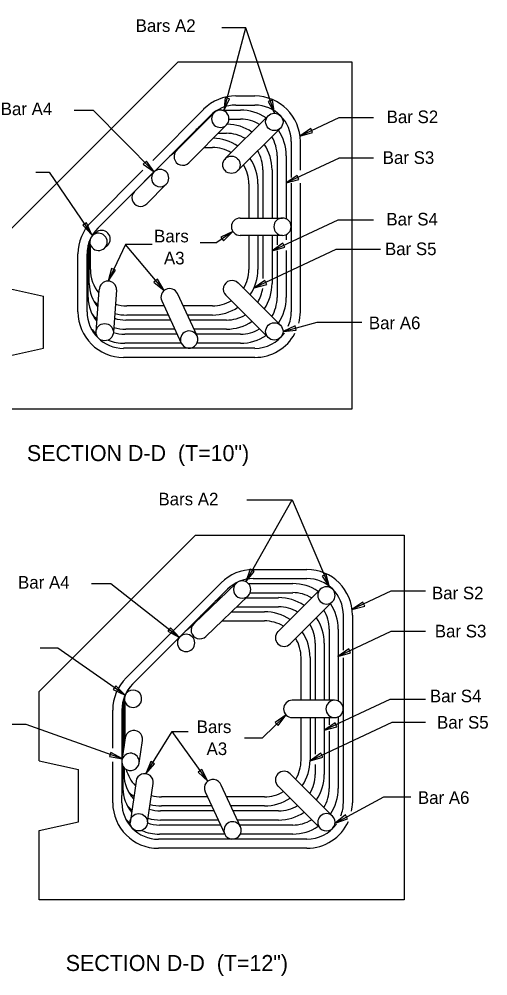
# Model space of a CAD drawing. Extents: x 0.4 to 30.8, y 0.2 to 19.4.
# Drawn here: x 9.71 to 15.33, y 0.99 to 12.47 of the extents above; entities that cross this region are included whole.
import ezdxf

# ---------------------------------------------------------------- set-up
doc = ezdxf.new("R2010")
doc.units = 0
for name, color, linetype in [('Dimension', 7, 'Continuous'), ('Rebar', 7, 'Continuous'), ('SheetPileConc', 7, 'Continuous'), ('TextStructures', 7, 'Continuous')]:
    doc.layers.add(name, color=color, linetype=linetype)

msp = doc.modelspace()

# ---------------------------------------------------------------- linework, layer by layer
at = {"layer": 'Dimension'}
for p, q in [((12.427, 12.366), (12.138, 12.366)), ((12.163, 11.368), (12.427, 12.366)), ((12.767, 11.341), (12.427, 12.366)), ((10.597, 11.375), (10.367, 11.375)), ((11.324, 10.637), (10.597, 11.375)), ((13.54, 11.285), (13.073, 11.066)), ((13.956, 11.285), (13.54, 11.285)), ((13.545, 10.803), (12.909, 10.505)), ((13.956, 10.803), (13.54, 10.803)), ((9.905, 10.633), (10.066, 10.633)), ((10.066, 10.633), (10.579, 9.884)), ((13.528, 10.06), (12.74, 9.69)), ((13.956, 10.06), (13.528, 10.06)), ((12.271, 9.922), (12.076, 9.789)), ((10.98, 9.767), (10.772, 9.327)), ((11.301, 9.767), (10.98, 9.767)), ((11.444, 9.214), (10.98, 9.767)), ((11.877, 9.789), (12.076, 9.789)), ((13.506, 9.707), (12.524, 9.246)), ((14.041, 9.707), (13.506, 9.707)), ((12.871, 8.724), (13.28, 8.834)), ((13.28, 8.834), (13.815, 8.834)), ((12.425, 5.722), (12.979, 6.704)), ((12.437, 6.704), (12.979, 6.704)), ((12.979, 6.704), (13.427, 5.656)), ((10.805, 5.696), (10.575, 5.696)), ((11.627, 5.052), (10.805, 5.696)), ((14.165, 5.607), (13.698, 5.388)), ((14.581, 5.607), (14.165, 5.607)), ((14.165, 5.124), (13.529, 4.826)), ((14.581, 5.124), (14.165, 5.124)), ((10.172, 4.926), (9.958, 4.926)), ((10.978, 4.362), (10.172, 4.926)), ((14.153, 4.311), (13.365, 3.941)), ((14.581, 4.311), (14.153, 4.311)), ((12.908, 4.125), (12.625, 3.849)), ((14.175, 4.033), (13.196, 3.573)), ((14.581, 4.033), (14.175, 4.033)), ((9.791, 4.01), (9.609, 4.01)), ((10.944, 3.596), (9.791, 4.01)), ((11.226, 3.419), (11.542, 3.925)), ((11.542, 3.925), (11.734, 3.925)), ((11.969, 3.33), (11.542, 3.925)), ((12.408, 3.849), (12.625, 3.849)), ((13.496, 2.828), (14.08, 3.141)), ((14.08, 3.141), (14.403, 3.141))]:
    msp.add_line(p, q, dxfattribs=at)
for points in [[(12.163, 11.368), (12.228, 11.512), (12.177, 11.526)], [(12.767, 11.341), (12.743, 11.497), (12.693, 11.481)], [(13.073, 11.066), (13.226, 11.109), (13.203, 11.157)], [(11.324, 10.637), (11.233, 10.767), (11.195, 10.73)], [(12.909, 10.505), (13.062, 10.547), (13.039, 10.595)], [(10.579, 9.884), (10.513, 10.028), (10.469, 9.998)], [(12.271, 9.922), (12.127, 9.856), (12.157, 9.812)], [(12.74, 9.69), (12.892, 9.733), (12.87, 9.781)], [(10.772, 9.327), (10.863, 9.457), (10.815, 9.48)], [(11.444, 9.214), (11.364, 9.35), (11.323, 9.316)], [(12.524, 9.246), (12.676, 9.288), (12.654, 9.336)], [(12.871, 8.724), (13.029, 8.739), (13.015, 8.79)], [(12.425, 5.722), (12.524, 5.845), (12.478, 5.871)], [(13.427, 5.656), (13.387, 5.809), (13.339, 5.788)], [(13.698, 5.388), (13.851, 5.43), (13.828, 5.478)], [(11.628, 5.052), (11.521, 5.17), (11.488, 5.128)], [(13.529, 4.826), (13.682, 4.868), (13.659, 4.916)], [(10.978, 4.363), (10.865, 4.474), (10.835, 4.43)], [(12.908, 4.125), (12.777, 4.035), (12.814, 3.997)], [(13.365, 3.941), (13.518, 3.983), (13.495, 4.031)], [(10.944, 3.596), (10.806, 3.673), (10.788, 3.624)], [(11.226, 3.419), (11.331, 3.538), (11.287, 3.566)], [(13.196, 3.573), (13.348, 3.616), (13.326, 3.664)], [(11.969, 3.33), (11.896, 3.47), (11.853, 3.438)], [(13.496, 2.828), (13.646, 2.879), (13.621, 2.925)]]:
    msp.add_lwpolyline(points, close=True, dxfattribs=at)
at = {"layer": 'Rebar'}
for p, q in [((12.306, 11.548), (12.532, 11.548)), ((11.92, 11.388), (11.308, 10.775)), ((12.137, 11.378), (12.362, 11.378)), ((12.306, 11.438), (12.532, 11.438)), ((12.045, 11.347), (11.601, 10.9)), ((11.997, 11.31), (11.722, 11.035)), ((12.179, 10.796), (12.694, 11.31)), ((12.223, 11.269), (12.362, 11.269)), ((11.828, 11.141), (10.65, 9.963)), ((12.192, 11.2), (11.742, 10.747)), ((12.327, 10.649), (12.841, 11.163)), ((12.092, 11.1), (12.193, 11.1)), ((11.607, 10.907), (11.594, 10.893)), ((11.924, 10.931), (12.024, 10.931)), ((12.969, 11.001), (12.969, 10.57)), ((13.078, 11.001), (13.078, 10.656)), ((12.8, 10.831), (12.8, 10.084)), ((12.909, 10.831), (12.909, 10.074)), ((11.188, 10.656), (10.572, 10.04)), ((11.089, 10.402), (11.323, 10.636)), ((12.63, 10.662), (12.63, 10.084)), ((12.74, 10.662), (12.74, 10.084)), ((11.236, 10.255), (11.471, 10.489)), ((12.461, 10.493), (12.461, 10.084)), ((12.571, 10.493), (12.571, 10.084)), ((12.969, 10.501), (12.969, 8.959)), ((13.078, 10.503), (13.078, 8.959)), ((12.357, 10.084), (12.865, 10.084)), ((10.624, 9.908), (10.587, 9.874)), ((12.865, 9.876), (12.357, 9.876)), ((12.461, 9.876), (12.461, 9.467)), ((12.571, 9.876), (12.571, 9.467)), ((12.63, 9.876), (12.63, 9.358)), ((12.74, 9.876), (12.74, 9.298)), ((12.8, 9.876), (12.8, 9.762)), ((12.909, 9.886), (12.909, 9.821)), ((10.534, 9.129), (10.534, 9.759)), ((10.547, 9.428), (10.547, 9.802)), ((10.56, 9.467), (10.56, 9.762)), ((10.729, 9.722), (10.768, 9.758)), ((10.412, 8.959), (10.412, 9.653)), ((10.521, 9.047), (10.521, 9.653)), ((12.8, 9.689), (12.8, 9.129)), ((12.909, 9.694), (12.909, 9.129)), ((10.547, 9.298), (10.547, 9.428)), ((12.333, 9.305), (12.841, 8.797)), ((10.628, 8.715), (10.667, 9.223)), ((10.875, 9.223), (10.836, 8.715)), ((11.416, 9.09), (11.651, 8.582)), ((11.84, 8.67), (11.605, 9.178)), ((12.694, 8.65), (12.186, 9.158)), ((10.521, 8.959), (10.521, 9.047)), ((11.444, 9.03), (10.998, 9.03)), ((12.024, 9.03), (11.674, 9.03)), ((11.522, 8.86), (10.985, 8.86)), ((11.495, 8.92), (10.998, 8.92)), ((12.024, 8.92), (11.724, 8.92)), ((12.193, 8.86), (11.752, 8.86)), ((11.573, 8.751), (10.985, 8.751)), ((12.193, 8.751), (11.802, 8.751)), ((11.6, 8.691), (10.972, 8.691)), ((12.362, 8.691), (11.83, 8.691)), ((12.532, 8.522), (10.959, 8.522)), ((11.651, 8.582), (10.972, 8.582)), ((12.362, 8.582), (11.839, 8.582)), ((12.532, 8.413), (10.959, 8.413)), ((12.515, 5.869), (13.157, 5.869)), ((12.515, 5.76), (13.157, 5.76)), ((12.128, 5.709), (10.989, 4.57)), ((11.401, 4.828), (12.205, 5.631)), ((12.309, 5.703), (11.806, 5.22)), ((12.456, 5.7), (12.987, 5.7)), ((12.811, 5.124), (13.319, 5.631)), ((11.947, 5.066), (12.453, 5.552)), ((12.43, 5.53), (12.818, 5.53)), ((12.478, 5.59), (12.987, 5.59)), ((12.316, 5.421), (12.818, 5.421)), ((13.466, 5.484), (12.958, 4.976)), ((11.93, 5.356), (11.765, 5.191)), ((12.254, 5.361), (12.649, 5.361)), ((13.594, 5.322), (13.594, 4.903)), ((13.703, 5.322), (13.703, 3.072)), ((11.765, 5.191), (11.066, 4.492)), ((12.14, 5.252), (12.649, 5.252)), ((13.425, 5.153), (13.425, 4.301)), ((13.534, 5.153), (13.534, 4.291)), ((13.256, 4.984), (13.256, 4.301)), ((13.365, 4.984), (13.365, 4.301)), ((13.086, 4.814), (13.086, 4.301)), ((13.196, 4.814), (13.196, 4.301)), ((13.594, 4.811), (13.594, 3.072)), ((10.964, 4.302), (10.964, 3.75)), ((10.977, 3.835), (10.977, 4.276)), ((13.49, 4.301), (12.982, 4.301)), ((10.829, 3.727), (10.829, 4.183)), ((10.938, 4.183), (10.938, 3.16)), ((10.951, 4.196), (10.951, 3.659)), ((12.982, 4.093), (13.49, 4.093)), ((13.086, 4.093), (13.086, 3.58)), ((13.196, 4.093), (13.196, 3.58)), ((13.256, 4.093), (13.256, 3.655)), ((13.365, 4.093), (13.365, 3.411)), ((13.425, 4.093), (13.425, 4.004)), ((13.534, 4.103), (13.534, 3.242)), ((13.425, 3.928), (13.425, 3.242)), ((10.978, 3.849), (10.939, 3.575)), ((11.145, 3.546), (11.184, 3.819)), ((10.829, 3.072), (10.829, 3.561)), ((10.951, 3.51), (10.951, 3.242)), ((10.964, 3.492), (10.964, 3.411)), ((13.256, 3.53), (13.256, 3.411)), ((11.108, 3.331), (11.036, 2.83)), ((13.466, 2.91), (12.958, 3.418)), ((11.244, 2.844), (11.314, 3.301)), ((12.361, 2.783), (12.13, 3.283)), ((12.811, 3.271), (13.319, 2.763)), ((10.938, 3.072), (10.938, 3.16)), ((11.965, 3.143), (11.415, 3.143)), ((11.937, 3.203), (12.172, 2.696)), ((12.649, 3.143), (12.195, 3.143)), ((12.016, 3.033), (11.415, 3.033)), ((12.649, 3.033), (12.245, 3.033)), ((12.043, 2.973), (11.402, 2.973)), ((12.818, 2.973), (12.273, 2.973)), ((12.121, 2.804), (11.389, 2.804)), ((12.094, 2.864), (11.402, 2.864)), ((12.818, 2.864), (12.323, 2.864)), ((12.987, 2.804), (12.351, 2.804)), ((12.172, 2.695), (11.389, 2.695)), ((12.987, 2.695), (12.36, 2.695)), ((13.157, 2.635), (11.376, 2.635)), ((13.157, 2.526), (11.376, 2.526))]:
    msp.add_line(p, q, dxfattribs=at)
for centre in [(12.767, 11.237), (12.253, 10.722), (10.732, 8.715), (12.767, 8.724), (11.14, 2.837)]:
    msp.add_circle(centre, 0.104, dxfattribs=at)
for centre, radius, start, end in [((12.306, 11.001), 0.547, 90, 134.9913), ((12.532, 11.001), 0.547, 0, 90), ((12.306, 11.001), 0.438, 90, 134.9913), ((12.119, 11.274), 0.104, 315.2149, 135.1708), ((12.137, 10.831), 0.547, 90, 95.9567), ((12.362, 10.831), 0.547, 55.9788, 90), ((12.532, 11.001), 0.438, 0, 90), ((12.119, 11.274), 0.104, 136.4105, 315.2348), ((12.362, 10.831), 0.438, 58.772, 90), ((12.137, 10.831), 0.438, 124.0426, 135), ((11.968, 10.662), 0.547, 96.7693, 98.1366), ((12.193, 10.662), 0.547, 55.9755, 89.1847), ((12.362, 10.831), 0.547, 0, 34.0266), ((11.968, 10.662), 0.438, 123.4477, 135), ((11.799, 10.493), 0.547, 96.6173, 98.1301), ((12.024, 10.493), 0.547, 55.9731, 89.0554), ((12.193, 10.662), 0.438, 58.7678, 90), ((12.362, 10.831), 0.438, 0, 31.2349), ((12.024, 10.493), 0.438, 58.7648, 90), ((12.193, 10.662), 0.547, 0, 34.0233), ((11.799, 10.493), 0.438, 120.5215, 135), ((11.668, 10.82), 0.104, 129.9409, 315.2357), ((12.024, 10.493), 0.547, 0, 34.0209), ((12.193, 10.662), 0.438, 0, 31.2307), ((12.024, 10.493), 0.438, 0, 31.2277), ((11.397, 10.563), 0.104, 135.0001, 315.0045), ((11.397, 10.563), 0.104, 315, 134.9998), ((11.163, 10.328), 0.104, 134.9779, 315.0221), ((10.959, 9.653), 0.547, 135, 180), ((12.357, 9.98), 0.104, 90.0071, 269.9929), ((12.865, 9.98), 0.104, 90.0227, 269.9756), ((12.865, 9.98), 0.104, 270, 90), ((10.959, 9.653), 0.438, 135, 180), ((10.658, 9.798), 0.104, 316.5108, 221.7293), ((10.695, 9.832), 0.104, 315, 132.8745), ((10.658, 9.798), 0.104, 221.7293, 314.4372), ((10.998, 9.467), 0.438, 180, 220.1905), ((12.024, 9.467), 0.438, 328.7684, 360), ((12.024, 9.467), 0.547, 325.9767, 360), ((10.985, 9.298), 0.438, 180, 220.2039), ((10.771, 9.223), 0.104, 0, 180), ((12.259, 9.231), 0.104, 45.0029, 225.0029), ((12.193, 9.298), 0.547, 325.978, 360), ((11.511, 9.134), 0.104, 24.7984, 204.7419), ((12.193, 9.298), 0.438, 328.7701, 352.2986), ((10.972, 9.129), 0.438, 180, 220.1919), ((10.998, 9.467), 0.547, 222.8908, 230.87), ((12.024, 9.467), 0.438, 270, 301.2314), ((12.362, 9.129), 0.438, 328.7717, 360), ((12.362, 9.129), 0.547, 325.9793, 360), ((10.959, 8.959), 0.547, 180, 270), ((10.959, 8.959), 0.438, 180, 270), ((10.998, 9.467), 0.438, 251.8586, 270), ((12.024, 9.467), 0.547, 270, 304.0244), ((12.532, 8.959), 0.438, 336.652, 360), ((12.532, 8.959), 0.547, 345.6268, 360), ((10.985, 9.298), 0.547, 222.9391, 230.8792), ((10.985, 9.298), 0.438, 251.8683, 270), ((10.998, 9.467), 0.547, 254.6455, 270), ((12.193, 9.298), 0.438, 270, 301.233), ((12.193, 9.298), 0.547, 270, 304.0257), ((10.972, 9.129), 0.547, 222.9167, 231.0732), ((10.985, 9.298), 0.547, 254.6532, 270), ((11.745, 8.626), 0.104, 24.7751, 203.3393), ((12.362, 9.129), 0.438, 270, 301.2347), ((10.972, 9.129), 0.547, 248.6363, 270), ((10.972, 9.129), 0.438, 251.8595, 270), ((11.745, 8.626), 0.104, 203.3393, 24.7751), ((12.362, 9.129), 0.547, 270, 304.027), ((12.532, 8.959), 0.438, 270, 324.3324), ((12.532, 8.959), 0.547, 270, 331.8725), ((12.515, 5.322), 0.547, 90, 135), ((13.157, 5.322), 0.547, 0, 90), ((12.515, 5.322), 0.438, 90, 135), ((13.157, 5.322), 0.438, 0, 90), ((12.381, 5.628), 0.104, 135, 315.0245), ((12.381, 5.628), 0.104, 315, 134.9767), ((12.987, 5.153), 0.547, 55.9787, 90), ((13.392, 5.558), 0.104, 135.0039, 315.0039), ((13.392, 5.558), 0.104, 315, 135), ((12.345, 5.153), 0.438, 118.5503, 135), ((12.176, 4.984), 0.547, 95.9443, 98.1301), ((12.818, 4.984), 0.547, 55.9765, 90), ((12.987, 5.153), 0.438, 58.7718, 90), ((12.818, 4.984), 0.438, 58.769, 90), ((12.987, 5.153), 0.547, 0, 34.0248), ((12.176, 4.984), 0.438, 121.166, 135), ((12.007, 4.814), 0.547, 95.9667, 98.1301), ((12.649, 4.814), 0.547, 55.9766, 90), ((12.818, 4.984), 0.547, 0, 34.0221), ((12.987, 5.153), 0.438, 0, 31.2323), ((12.007, 4.814), 0.438, 121.08, 135), ((11.912, 5.043), 0.208, 118.7822, 135), ((11.873, 5.14), 0.104, 130.2199, 315.0091), ((12.649, 4.814), 0.438, 58.7692, 90), ((12.818, 4.984), 0.438, 0, 31.2289), ((11.709, 4.988), 0.104, 135.0001, 315), ((11.709, 4.988), 0.104, 315.0002, 134.9995), ((12.884, 5.05), 0.104, 134.9993, 314.9804), ((12.649, 4.814), 0.547, 0, 34.0217), ((12.649, 4.814), 0.438, 0, 31.2301), ((11.376, 4.183), 0.547, 135, 180), ((11.376, 4.183), 0.438, 135, 180), ((11.389, 4.196), 0.438, 135, 153.6351), ((11.072, 4.319), 0.104, 315, 225.1883), ((11.389, 4.196), 0.438, 163.9734, 180), ((12.982, 4.197), 0.104, 90.0337, 269.9664), ((13.49, 4.197), 0.104, 90.0227, 269.9754), ((13.49, 4.197), 0.104, 270, 90), ((11.072, 4.319), 0.104, 225.1883, 314.9716), ((11.081, 3.834), 0.104, 351.8606, 171.8873), ((11.042, 3.561), 0.104, 351.8732, 231.3288), ((12.649, 3.58), 0.438, 328.7552, 0), ((12.649, 3.58), 0.547, 325.9681, 0), ((11.042, 3.561), 0.104, 231.3288, 351.8732), ((11.415, 3.58), 0.438, 194.6287, 223.9951), ((12.884, 3.345), 0.104, 45.014, 225.0062), ((11.402, 3.411), 0.438, 180, 222.1318), ((11.211, 3.316), 0.104, 351.2929, 171.8392), ((12.032, 3.247), 0.104, 20.0236, 204.7419), ((12.818, 3.411), 0.438, 328.7619, 360), ((12.818, 3.411), 0.547, 325.9733, 360), ((11.389, 3.242), 0.438, 180, 220.1986), ((12.987, 3.242), 0.438, 328.7685, 360), ((12.987, 3.242), 0.547, 325.9785, 360), ((11.415, 3.58), 0.547, 222.8885, 232.4453), ((11.415, 3.58), 0.438, 253.7554, 270), ((12.649, 3.58), 0.438, 270, 301.2421), ((12.649, 3.58), 0.547, 270, 304.0311), ((11.376, 3.072), 0.547, 180, 270), ((11.376, 3.072), 0.438, 180, 270), ((11.402, 3.411), 0.547, 222.9253, 231.1025), ((11.402, 3.411), 0.438, 252.0732, 270), ((11.415, 3.58), 0.547, 255.2692, 270), ((12.818, 3.411), 0.438, 270, 301.2388), ((13.157, 3.072), 0.438, 338.9894, 360), ((13.157, 3.072), 0.547, 349.152, 360), ((11.389, 3.242), 0.547, 222.9236, 229.9392), ((11.402, 3.411), 0.547, 253.9287, 270), ((12.818, 3.411), 0.547, 270, 304.0285), ((13.392, 2.837), 0.104, 44.996, 224.996), ((13.392, 2.837), 0.104, 224.996, 45.0161), ((11.389, 3.242), 0.438, 250.6572, 270), ((12.266, 2.739), 0.104, 24.7751, 204.7499), ((12.266, 2.739), 0.104, 204.7499, 24.7943), ((12.987, 3.242), 0.438, 270, 301.2355), ((12.987, 3.242), 0.547, 270, 304.0258), ((13.157, 3.072), 0.547, 270, 335.7711), ((13.157, 3.072), 0.438, 270, 323.9148), ((11.389, 3.242), 0.547, 246.9407, 270)]:
    msp.add_arc(centre, radius, start, end, dxfattribs=at)
at = {"layer": 'SheetPileConc'}
for p, q in [((11.615, 11.959), (9.532, 9.876)), ((11.615, 11.959), (13.698, 11.959)), ((13.698, 11.959), (13.698, 7.793)), ((9.532, 9.251), (10, 9.147)), ((10, 8.522), (10, 9.147)), ((9.532, 8.418), (10, 8.522)), ((13.698, 7.793), (9.532, 7.793)), ((11.823, 6.281), (9.948, 4.406)), ((11.823, 6.281), (14.323, 6.281)), ((14.323, 6.281), (14.323, 1.906)), ((9.948, 3.572), (9.948, 4.406)), ((9.948, 3.572), (10.417, 3.468)), ((10.417, 2.843), (10.417, 3.468)), ((9.948, 2.739), (10.417, 2.843)), ((9.948, 1.906), (9.948, 2.739)), ((14.323, 1.906), (9.948, 1.906))]:
    msp.add_line(p, q, dxfattribs=at)

# ---------------------------------------------------------------- texts
at = {"layer": 'Dimension'}
for s, p in [('Bars', (11.325, 9.792)), ('A3', (11.443, 9.528)), ('Bars', (11.836, 3.907)), ('A3', (11.954, 3.643))]:
    msp.add_text(s, height=0.1512, dxfattribs=at).set_placement(p)
at = {"layer": 'TextStructures'}
for s, height, p in [('Bars A2', 0.1512, (11.104, 12.316)), ('Bar A4', 0.1512, (9.485, 11.318)), ('Bar S2', 0.1512, (14.114, 11.222)), ('Bar S3', 0.1512, (14.067, 10.733)), ('Bar S4', 0.1512, (14.111, 9.995)), ('Bar S5', 0.1512, (14.094, 9.639)), ('Bar A6', 0.1512, (13.901, 8.751)), ('SECTION D-D  (T=10") ', 0.192, (9.799, 7.169)), ('Bars A2', 0.1512, (11.377, 6.638)), ('Bar A4', 0.1512, (9.693, 5.639)), ('Bar S2', 0.1512, (14.658, 5.511)), ('Bar S3', 0.1512, (14.692, 5.054)), ('Bar S4', 0.1512, (14.633, 4.276)), ('Bar S5', 0.1512, (14.719, 3.96)), ('Bar A6', 0.1512, (14.489, 3.057)), ('SECTION D-D  (T=12") ', 0.192, (10.265, 1.053))]:
    msp.add_text(s, height=height, dxfattribs=at).set_placement(p)

doc.saveas('drawing.dxf')
